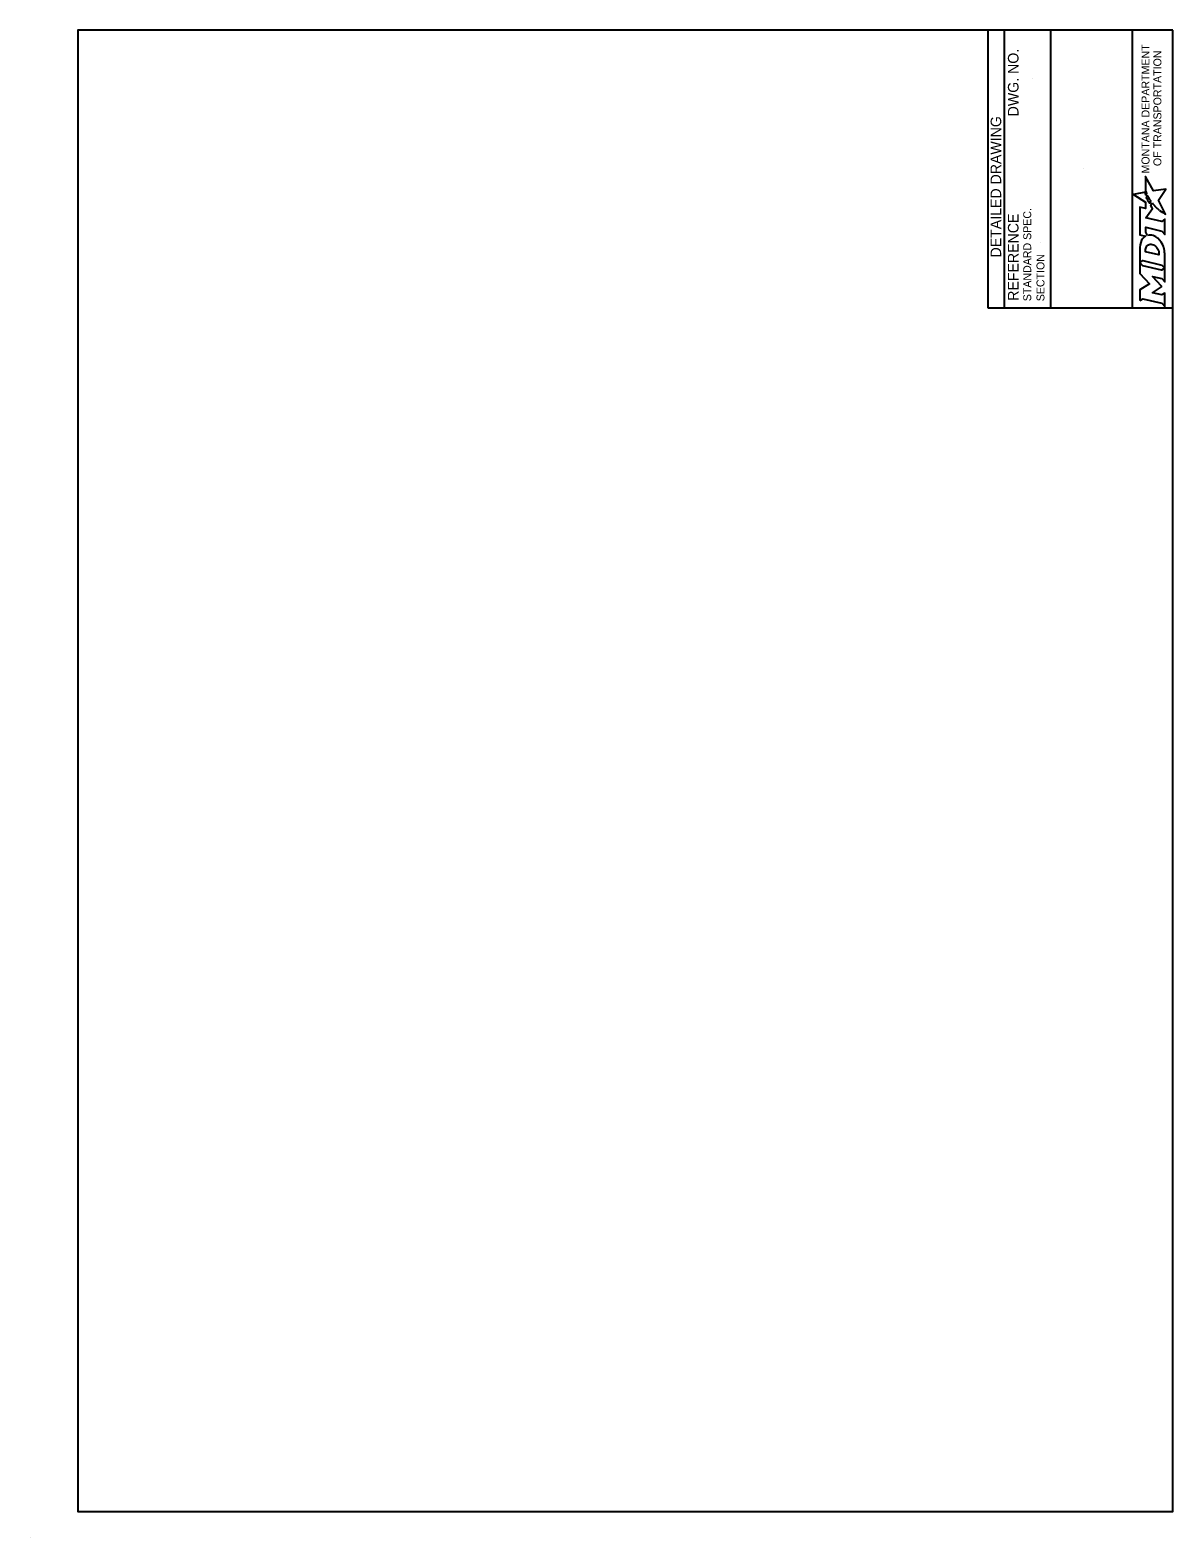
# Model space of a CAD drawing. Extents: x 49991.4 to 50021, y 49987.6 to 50011.4.
# Drawn here: x 49999.98 to 50008.61, y 49999.86 to 50011.26 of the extents above; entities that cross this region are included whole.
import ezdxf

# ---------------------------------------------------------------- set-up
doc = ezdxf.new("R2010")
doc.units = 0
doc.layers.add('Level 1', color=7, linetype='Continuous')
doc.layers.add('Level 3', color=7, linetype='Continuous')

msp = doc.modelspace()

# ---------------------------------------------------------------- linework, layer by layer
at = {"layer": 'Level 1'}
msp.add_line((49999.977, 49999.862), (49999.977, 49999.862), dxfattribs=at)
msp.add_lwpolyline([(50008.615, 50011.263), (50000.336, 50011.263), (50000.336, 50000.062), (50008.615, 50000.062)], close=True, dxfattribs=at)
at = {"layer": 'Level 3'}
for p, q in [((50007.215, 50011.263), (50007.215, 50009.163)), ((50007.34, 50011.263), (50007.34, 50009.163)), ((50007.69, 50011.263), (50007.69, 50009.163)), ((50008.308, 50011.263), (50008.308, 50009.163)), ((50007.555, 50010.899), (50007.555, 50010.899)), ((50007.939, 50010.213), (50007.939, 50010.213)), ((50007.614, 50009.657), (50007.614, 50009.657)), ((50007.215, 50009.163), (50008.615, 50009.163))]:
    msp.add_line(p, q, dxfattribs=at)
for points in [[(50008.514, 50009.9), (50008.538, 50009.885), (50008.546, 50009.88), (50008.554, 50009.875), (50008.559, 50009.872), (50008.505, 50009.978), (50008.561, 50010.061), (50008.468, 50010.048), (50008.409, 50010.155), (50008.409, 50010.106), (50008.408, 50010.076), (50008.408, 50010.055), (50008.409, 50010.048), (50008.411, 50010.043), (50008.413, 50010.035), (50008.417, 50010.025)], [(50008.417, 50010.025), (50008.411, 50010.014), (50008.409, 50010.026), (50008.407, 50010.038), (50008.316, 50010.02), (50008.408, 50009.961), (50008.408, 50009.914), (50008.364, 50009.924), (50008.364, 50009.715), (50008.407, 50009.705), (50008.398, 50009.699)], [(50008.423, 50009.711), (50008.41, 50009.736), (50008.41, 50009.773), (50008.531, 50009.744), (50008.553, 50009.717), (50008.553, 50009.833), (50008.531, 50009.816), (50008.41, 50009.844), (50008.462, 50009.915), (50008.447, 50009.937), (50008.458, 50009.956)], [(50008.445, 50009.974), (50008.446, 50009.972), (50008.437, 50009.954), (50008.431, 50009.964), (50008.429, 50009.968), (50008.425, 50009.977), (50008.422, 50009.982), (50008.419, 50009.99), (50008.416, 50009.998), (50008.424, 50010.009), (50008.426, 50010.005), (50008.428, 50010.001), (50008.431, 50009.997), (50008.434, 50009.992), (50008.435, 50009.99), (50008.436, 50009.987), (50008.438, 50009.985), (50008.439, 50009.982), (50008.441, 50009.98), (50008.443, 50009.977), (50008.445, 50009.974)], [(50008.498, 50009.914), (50008.498, 50009.914)], [(50008.364, 50009.62), (50008.364, 50009.506), (50008.387, 50009.521), (50008.531, 50009.487), (50008.553, 50009.462), (50008.553, 50009.572)], [(50008.451, 50009.644), (50008.459, 50009.643), (50008.468, 50009.64), (50008.476, 50009.635), (50008.484, 50009.63), (50008.491, 50009.623), (50008.497, 50009.615), (50008.502, 50009.607), (50008.506, 50009.598), (50008.508, 50009.589), (50008.509, 50009.58), (50008.509, 50009.564), (50008.409, 50009.587), (50008.409, 50009.603), (50008.41, 50009.611), (50008.412, 50009.619), (50008.415, 50009.625), (50008.419, 50009.631), (50008.424, 50009.636), (50008.43, 50009.64), (50008.436, 50009.642), (50008.443, 50009.644), (50008.446, 50009.644), (50008.451, 50009.644)], [(50008.546, 50009.618), (50008.543, 50009.626), (50008.538, 50009.639), (50008.527, 50009.66)], [(50008.387, 50009.481), (50008.364, 50009.506), (50008.364, 50009.424), (50008.437, 50009.344), (50008.364, 50009.3), (50008.364, 50009.218)], [(50008.364, 50009.218), (50008.388, 50009.232), (50008.531, 50009.198), (50008.553, 50009.173), (50008.553, 50009.274), (50008.531, 50009.261), (50008.461, 50009.277), (50008.53, 50009.321), (50008.53, 50009.326), (50008.46, 50009.401), (50008.531, 50009.385), (50008.553, 50009.36), (50008.553, 50009.462), (50008.53, 50009.448), (50008.387, 50009.481)]]:
    msp.add_lwpolyline(points, dxfattribs=at)
for centre, radius, start, end in [((50008.443, 50009.643), 0.0709, 69.5329, 105.8582), ((50008.425, 50009.599), 0.118, 30.9103, 69.1383)]:
    msp.add_arc(centre, radius, start, end, dxfattribs=at)
for centre, major_axis, ratio, start_param, end_param in [((50008.468, 50009.945), (0.0097, -0.0112), 0.021651, 3.157348, 6.283185), ((50008.487, 50009.924), (0.0102, -0.0098), 0.016458, 3.141593, 6.279097), ((50008.506, 50009.907), (0.00806, -0.00694), 0.008222, 0, 3.137361), ((50008.412, 50009.618), (0.0037, 0.0834), 0.568097, 0.61298, 1.570796), ((50008.404, 50009.673), (0.0295, 0.0361), 0.469099, 1.225588, 1.570796), ((50008.405, 50009.573), (-0.148, 0), 0.987302, 3.139398, 3.456847)]:
    msp.add_ellipse(centre, major_axis=major_axis, ratio=ratio, start_param=start_param, end_param=end_param, dxfattribs=at)

# ---------------------------------------------------------------- texts
for s, height, p in [('DWG. NO.', 0.08, (50007.448, 50010.611)), ('MONTANA DEPARTMENT', 0.06, (50008.438, 50010.179)), ('OF TRANSPORTATION', 0.06, (50008.528, 50010.235)), ('DETAILED DRAWING', 0.0799, (50007.317, 50009.544)), ('STANDARD SPEC.', 0.06, (50007.544, 50009.213)), ('REFERENCE', 0.08, (50007.448, 50009.216)), ('SECTION', 0.06, (50007.644, 50009.213))]:
    msp.add_text(s, height=height, rotation=90, dxfattribs=at).set_placement(p)

doc.saveas('drawing.dxf')
